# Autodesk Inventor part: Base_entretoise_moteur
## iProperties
Shininess: 64.0
Length Units: 11269
Angle Units: 11279
Time Units: 11290
Mass Units: 11283
Length Display Precision: 3
Angle Display Precision: 2
Compacted: True
Part Number: Base_entretoise_moteur
Document SubType Name: Modeling
Created: 2008-02
Material: Acier inoxydable - 440C
Designer: Pascal
Density: 0.0
Volumn: 0.0
Area: 0.0
PropertySet Name: Model Information
Control State: 0
Master: False
Checked Out: False
DESIGNATION: pièce
Author: Pascal
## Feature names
1. Extrusion1
2. Extrusion2
3. Réseau circulaire1 [Circular Pattern]
